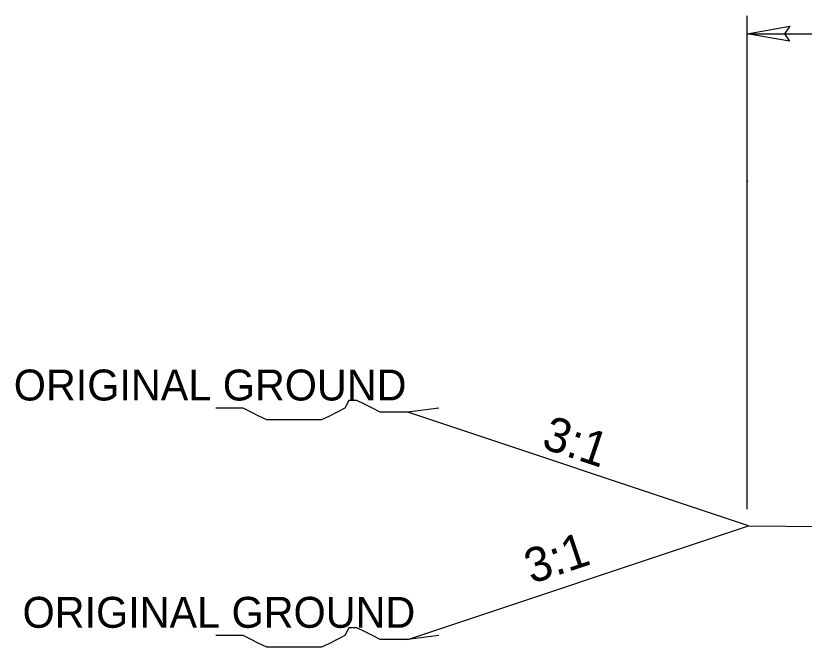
# Model space of a CAD drawing. Extents: x 958711 to 962106, y 831169 to 840840.
# Drawn here: x 959196.2 to 959374.8, y 835348.4 to 835491.3 of the extents above; entities that cross this region are included whole.
import ezdxf

# ---------------------------------------------------------------- set-up
doc = ezdxf.new("R2010")
doc.units = 0
for name, color, linetype in [('Old_Level_1', 7, 'Continuous'), ('Old_Level_11', 7, 'Continuous'), ('Old_Level_21', 7, 'Continuous'), ('Old_Level_3', 7, 'Continuous')]:
    doc.layers.add(name, color=color, linetype=linetype)

msp = doc.modelspace()

# ---------------------------------------------------------------- linework, layer by layer
at = {"layer": 'Old_Level_1'}
for p, q in [((959361.86, 835379.68), (959361.86, 835491.34)), ((959361.86, 835487.29), (959418.82, 835487.29)), ((959362.17, 835375.89), (959284.99, 835401.62)), ((959284.99, 835350.16), (959362.17, 835375.89)), ((959362.17, 835375.89), (959415.26, 835375.36))]:
    msp.add_line(p, q, dxfattribs=at)
at = {"layer": 'Old_Level_11'}
for points in [[(959371.47, 835485.63), (959361.86, 835487.29), (959371.52, 835489), (959370.3, 835487.29)], [(959361.99, 835453.9), (959361.86, 835453.92), (959361.99, 835453.95), (959361.98, 835453.92)]]:
    msp.add_lwpolyline(points, close=True, dxfattribs=at)
at = {"layer": 'Old_Level_21'}
for points in [[(959292.08, 835402.5), (959284.99, 835401.62), (959283.21, 835401.62), (959280.55, 835401.62), (959278.77, 835401.62), (959277.01, 835402.5), (959275.23, 835403.4), (959273.46, 835404.28), (959271.68, 835404.28), (959270.79, 835402.5), (959269.02, 835401.62), (959267.25, 835400.72), (959265.48, 835399.85), (959263.7, 835399.85), (959261.93, 835399.85), (959260.15, 835399.85), (959258.38, 835399.85), (959256.61, 835399.85), (959254.84, 835399.85), (959253.06, 835399.85), (959251.29, 835400.72), (959249.52, 835401.62), (959247.75, 835402.5), (959245.08, 835402.5), (959243.31, 835402.5), (959241.53, 835402.5)], [(959292.08, 835351.04), (959284.99, 835350.16), (959283.21, 835350.16), (959280.55, 835350.16), (959278.77, 835350.16), (959277.01, 835351.04), (959275.23, 835351.93), (959273.46, 835352.81), (959271.68, 835352.81), (959270.79, 835351.04), (959269.02, 835350.16), (959267.25, 835349.26), (959265.48, 835348.39), (959263.7, 835348.39), (959261.93, 835348.39), (959260.15, 835348.39), (959258.38, 835348.39), (959256.61, 835348.39), (959254.84, 835348.39), (959253.06, 835348.39), (959251.29, 835349.26), (959249.52, 835350.16), (959247.75, 835351.04), (959245.08, 835351.04), (959243.31, 835351.04), (959241.53, 835351.04)]]:
    msp.add_lwpolyline(points, dxfattribs=at)

# ---------------------------------------------------------------- texts
for p in [(959195.78, 835404.25), (959197.77, 835352.79)]:
    msp.add_text('ORIGINAL GROUND', height=7, dxfattribs=at).set_placement(p)
at = {"layer": 'Old_Level_3'}
for rotation, p in [(341.5652, (959315.02, 835393.58)), (18.4348, (959313.05, 835362.67))]:
    msp.add_text('3:1', height=7.801, rotation=rotation, dxfattribs=at).set_placement(p)

doc.saveas('drawing.dxf')
